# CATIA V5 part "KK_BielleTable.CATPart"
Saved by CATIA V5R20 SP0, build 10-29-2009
Part number: bielle table 1_2
Bounding box of the stored display mesh (mm): x -1002.373 to 342.501, y -156.493 to -111.493, z 0 to 70
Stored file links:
  G:\Khaled_CFAO_2011\ST2M\ST2M_GR2\tcorbin\Khaled\CAD_ThinkMOTION\KK_BielleTable.CATPart
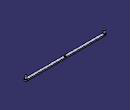
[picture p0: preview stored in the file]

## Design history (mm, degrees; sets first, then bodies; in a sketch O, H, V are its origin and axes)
Body1 (main body)
  Sketch1 on xy-plane, origin (0, 0, 0), H (1, 0, 0), V (0, 1, 0)
    line L1 (-979.9356, -111.4934) -> (320.0644, -111.4934)
    arc A1 centre (320.0644, -133.9934) radius 22.5 from (320.0644, -111.4934) to (320.0644, -156.4934) cw
    line L2 (320.0644, -156.4934) -> (-979.9356, -156.4934)
    arc A2 centre (-979.9356, -133.9934) radius 22.5 from (-979.9356, -156.4934) to (-979.9356, -111.4934) cw
    length L1 = 1300
    distance L1 L2 = 45
    length L2 = 1300
    tangency: A1 L1, L2 A1, A2 L2
    horizontal: L1 H, L2 H
  Pad1: profile Sketch1, direction (0, 0, 1), length 20
  Sketch2 on end face of Pad1, origin (0, 0, 20), H (1, 0, 0), V (0, 1, 0)
    circle A1 centre (320.0644, -133.9934) radius 15
    reference projected arc E1 centre (320.0644, -133.9934) radius 22.5 from (320.0644, -156.4934) to (320.0644, -111.4934) ccw from edge [face of Pad1 from Sketch1.A1 | end face of Pad1]
    circle A2 centre (-979.9356, -133.9934) radius 15
    reference projected arc E2 centre (-979.9356, -133.9934) radius 22.5 from (-979.9356, -111.4934) to (-979.9356, -156.4934) ccw from edge [face of Pad1 from Sketch1.A2 | end face of Pad1]
    concentricity: A1 E1, A2 E2
  Pad2: profile Sketch2, direction (0, 0, 1), length 50
  Sketch3 on end face of Pad1, origin (-305.2924, -144.6, 20), H (1, 0, 0), V (0, 1, 0)
    point P1 (-24.6432, 10.6066)
    reference projected line E1 (-674.6432, -11.8934) -> (625.3568, -11.8934) from edge [face of Pad1 from Sketch1.L2 | end face of Pad1]
    reference projected circle E2 centre (625.3568, 10.6066) radius 15 from edge [face of Pad2 from Sketch2.A1 | end face of Pad2]
    distance P1 E1 = 22.5
    distance P1 E2 = 665
  Hole1: placed by Sketch3, at (-329.9356, -133.9934, 20) direction (0, 0, -1), diameter 30, through (limit type 3)
  Boundary1: Boundary face of Pad2 from Sketch2.A2
  Extract1: ExtractElem edge of Boundary1
  Boundary2: Boundary face of Pad2 from Sketch2.A1
  Extract2: ExtractElem edge of Boundary2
